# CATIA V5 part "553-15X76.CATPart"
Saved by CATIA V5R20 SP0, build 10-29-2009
Part number: 553-15X76
Definition: NONE
Nomenclature: 553-15X76
Source: Unknown
Description: 553-15X76
Bounding box of the stored display mesh (mm): x 0 to 76, y -12.5 to 12.5, z -12.5 to 12.5
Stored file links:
  C:\Users\Utente\Desktop\IO LAVORO\3D X SITO CF\X SITO\PLASTICA\553\553-15X76.CATPart
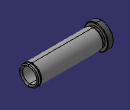
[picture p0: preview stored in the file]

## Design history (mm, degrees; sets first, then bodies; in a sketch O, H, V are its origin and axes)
Body1 "553-15X76" (main body)
  Solid1: solid without history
